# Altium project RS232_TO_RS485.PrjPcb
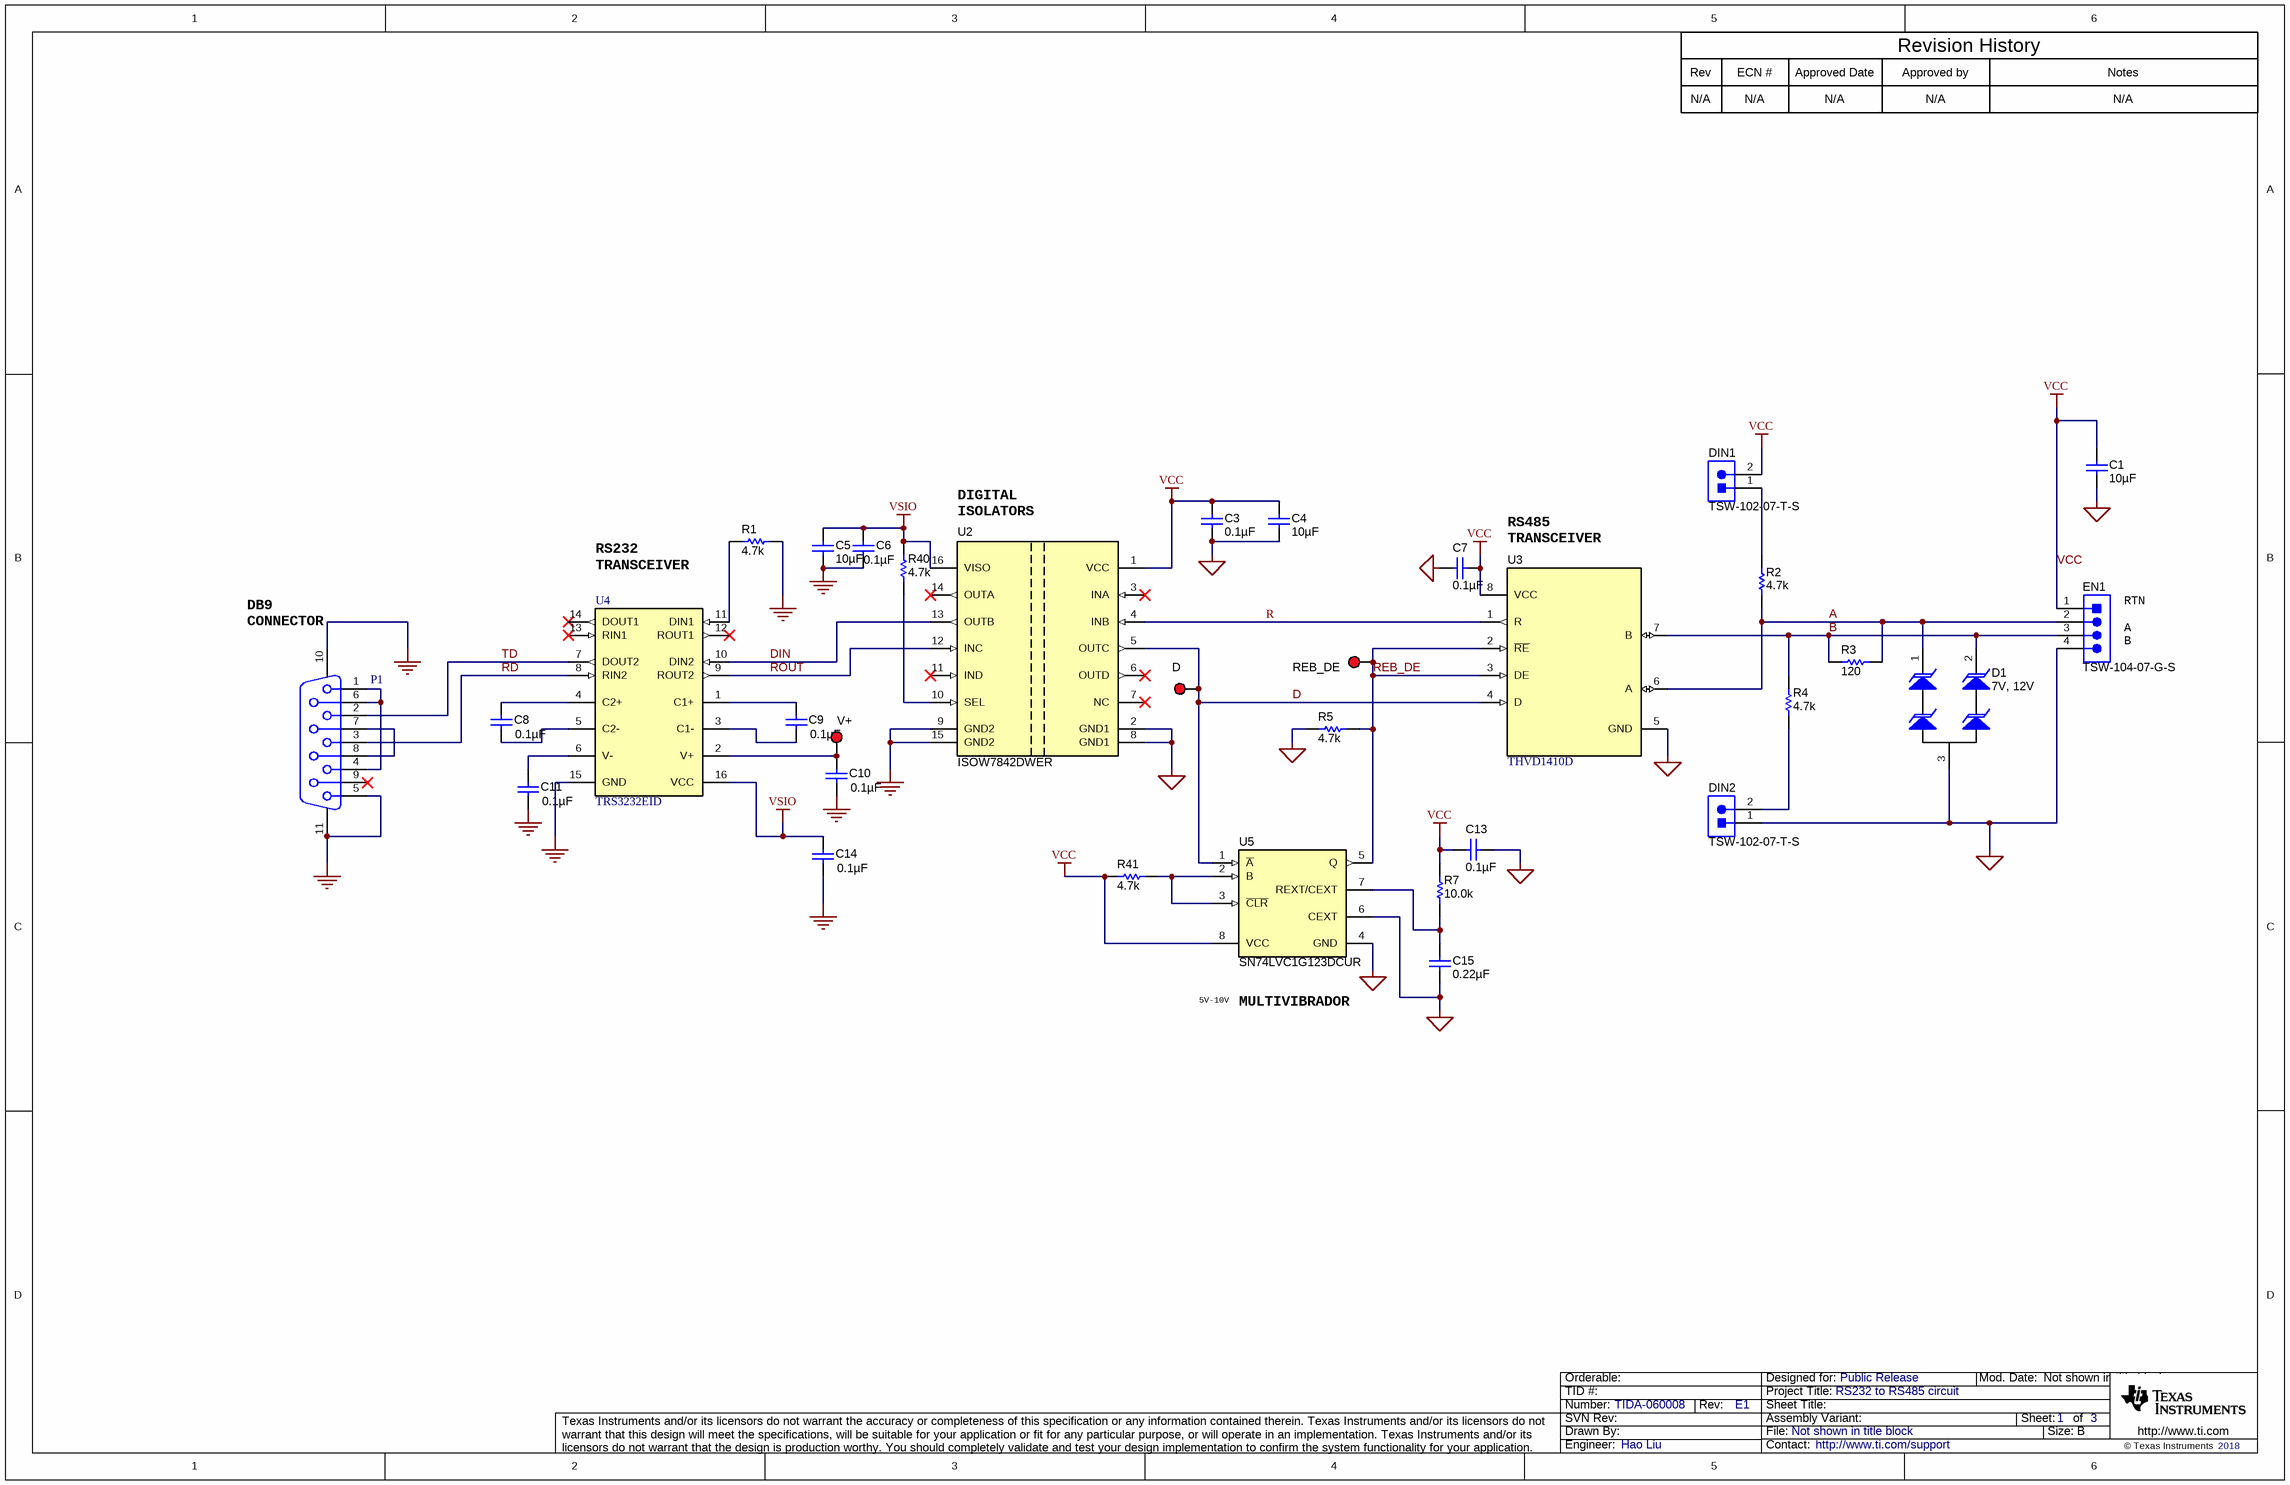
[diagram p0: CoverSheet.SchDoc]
TIDA: 060008; TechSupport: http://www.ti.com/support; SCH_Rev: E1; PRJ_Title: RS232 to RS485 circuit; PRJ_Number: TIDA-060008; PRJ_Engineer: Hao Liu; PRJ_Customer: Public Release; PCB_Rev: E1; PCB_Layout: Hao Liu; CopyrightYear: 2018
3 sheets, 49 parts. Net scope: global (net labels, ports and power ports of the same name join across sheets).
Board file: PCB.PcbDoc
Sheets:
  CoverSheet.SchDoc
  BlankSheet.SchDoc
  EVM_Hardware.SchDoc

## Sheet CoverSheet.SchDoc
size 431 x 279 mm; Date: Not shown in title block; ApprovedBy: Not shown in title block; CheckedBy: Not shown in title block; Author: Not shown in title block; CompanyName: Not shown in title block; Engineer: Not shown in title block; Organization: Not shown in title block; Address1: Not shown in title block; Address2: Not shown in title block; Address3: Not shown in title block; Address4: Not shown in title block; DocumentNumber: 1; Revision: Use project parameter SCH_Rev; SheetNumber: 1; SheetTotal: 3; PageSetup: Record=PageOptions¦CenterHorizontal=True¦CenterVertical=True¦PrintScale=1.00¦XCorrection=1.00¦YCorrection=1.00¦PrintKind=0¦BorderSize=5000000¦LeftOffset=0¦BottomOffset=0¦Orientation=2¦PaperLength=1000¦PaperWidth=1000¦Scale=100¦PaperSource=15¦PrintQuality=600¦MediaType=1¦DitherType=10¦PaperKind=Letter¦PrintScaleMode=1

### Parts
C1  ValueDisplayed: 10µF  [0805_HV]  (hidden comment: EMK212BJ106KG-T)
C3  ValueDisplayed: 0.1µF  [0603]  (hidden comment: GCM188R71C104KA37J)
C4  ValueDisplayed: 10µF  [0805_HV]  (hidden comment: GRM21BC80J106KE19L)
C5  ValueDisplayed: 10µF  [0805_HV]  (hidden comment: GRM21BC80J106KE19L)
C6  ValueDisplayed: 0.1µF  [0603]  (hidden comment: GCM188R71C104KA37J)
C7  ValueDisplayed: 0.1µF  [0603]  (hidden comment: GCM188R71C104KA37J)
C8  ValueDisplayed: 0.1µF  [0603]  (hidden comment: GCM188R71C104KA37J)
C9  ValueDisplayed: 0.1µF  [0603]  (hidden comment: GCM188R71C104KA37J)
C10  ValueDisplayed: 0.1µF  [0603]  (hidden comment: GCM188R71C104KA37J)
C11  ValueDisplayed: 0.1µF  [0603]  (hidden comment: GCM188R71C104KA37J)
C13  ValueDisplayed: 0.1µF  [0603]  (hidden comment: GCM188R71C104KA37J)
C14  ValueDisplayed: 0.1µF  [0603]  (hidden comment: GCM188R71C104KA37J)
C15  ValueDisplayed: 0.22µF  [0603]  (hidden comment: GRM188R70J224KA88D)
D  5000  [Keystone5000]  (value not drawn)
D1  value 7V, 12V  [SOT-23]  (hidden comment: SM712.TCT)
DIN1  TSW-102-07-T-S  [Samtec_TSW-102-07-T-S]
DIN2  TSW-102-07-T-S  [Samtec_TSW-102-07-T-S]
EN1  TSW-104-07-G-S  [TSW-104-07-G-S]
P1  1734354-1  [TE_1734354-1]  (value not drawn)
R1  ValueDisplayed: 4.7k  [0603]  (hidden comment: ERJ-3GEYJ472V)
R2  ValueDisplayed: 4.7k  [0603]  (hidden comment: ERJ-3GEYJ472V)
R3  ValueDisplayed: 120  [0603]  (hidden comment: CRCW0603120RJNEA)
R4  ValueDisplayed: 4.7k  [0603]  (hidden comment: ERJ-3GEYJ472V)
R5  ValueDisplayed: 4.7k  [0603]  (hidden comment: ERJ-3GEYJ472V)
R7  ValueDisplayed: 10.0k  [0603]  (hidden comment: RMCF0603FT10K0)
R40  ValueDisplayed: 4.7k  [0603]  (hidden comment: ERJ-3GEYJ472V)
R41  ValueDisplayed: 4.7k  [0603]  (hidden comment: ERJ-3GEYJ472V)
REB_DE  5000  [Keystone5000]  (value not drawn)
U2  ISOW7842DWER  [DWE0016A]
U3  THVD1410D  [D0008A_N]
U4  TRS3232EID  [D0016A_N]
U5  SN74LVC1G123DCUR  [DCU0008A_N]
V+  5000  [Keystone5000]  (value not drawn)

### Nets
GND: C5.2 C6.2 C10.2 C11.2 C14.2 P1.5 P1.10 P1.11 R1.2 U2.9(GND2) U2.15(GND2) U4.15(GND)
GND_SIGNAL: C1.2 C3.2 C4.2 C7.2 C13.1 C15.2 D1.3 DIN2.1 EN1.4 R5.1 U2.2(GND1) U2.8(GND1) U3.5(GND) U5.4(GND) U5.6(CEXT)
VCC: C1.1 C3.1 C4.1 C7.1 C13.2 DIN1.2 EN1.1 R7.2 R41.2 U2.1(VCC) U3.8(VCC) U5.8(VCC)
VSIO: C5.1 C6.1 C14.1 R40.2 U2.16(VISO) U4.16(VCC)
A: D1.1 EN1.2 R2.1 R3.2 U3.6(A)
B: D1.2 EN1.3 R3.1 R4.2 U3.7(B)
D: D.1 U2.5(OUTC) U3.4(D) U5.1(~{A})
DIN: U2.13(OUTB) U4.10(DIN2)
R: U2.4(INB) U3.1(R)
RD: P1.3 U4.8(RIN2)
REB_DE: R5.2 REB_DE.1 U3.2(~{RE}) U3.3(DE) U5.5(Q)
ROUT: U2.12(INC) U4.9(ROUT2)
TD: P1.2 U4.7(DOUT2)
NetC8_1: C8.1 U4.4(C2+)
NetC8_2: C8.2 U4.5(C2-)
NetC9_1: C9.1 U4.1(C1+)
NetC9_2: C9.2 U4.3(C1-)
NetC10_1: C10.1 U4.2(V+) V+.1
NetC11_1: C11.1 U4.6(V-)
NetC15_1: C15.1 R7.1 U5.7(REXT/CEXT)
NetDIN1_1: DIN1.1 R2.2
NetDIN2_2: DIN2.2 R4.1
NetP1_1: P1.1 P1.4 P1.6
NetP1_7: P1.7 P1.8
NetR1_1: R1.1 U4.11(DIN1)
NetR40_1: R40.1 U2.10(SEL)
NetR41_1: R41.1 U5.2(B) U5.3(~{CLR})

Not connected (* = marked no-connect by the designer): P1 9*; U2 3(INA)* 6(OUTD)* 7(NC)* 11(IND)* 14(OUTA)*; U4 12(ROUT1)* 13(RIN1)* 14(DOUT1)*

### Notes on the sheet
- Rev
- N/A
- ECN #
- Approved Date
- Approved by
- Revision History
- Notes
- DIGITAL
  ISOLATORS
- RS485
  TRANSCEIVER
- (near P1) DB9
  CONNECTOR
- (near R1) RS232
  TRANSCEIVER
- (near EN1) A
- (near EN1) RTN
- (near EN1) B
- 5V-10V
- (near U5) MULTIVIBRADOR

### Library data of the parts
C1 = EMK212BJ106KG-T: CAP, CERM, 10 µF, 16 V,+/- 10%, X5R, 0805; Manufacturer: Taiyo Yuden; Polarized: N; CompType: Capacitor; Value: 10uF; U/M: EA; Cap_F: 0.00001; Tolerance_%: 10; VDC_V: 16; Value2: 16V; TaMin_C: -55; TaMax_C: 85; Cap_Case: 0805; SizeArea_mm2: 2.5; SizeAreaWB_mm2: 6.75; SizeX_mm: 2; SizeY_mm: 1.25; SizeZ_mm: 1.45; AEC Category: Q200; Green_Lifecycle: Not Set; Green_REACh: Incomplete
C3 C6 C7 C13 = GCM188R71C104KA37J: CAP, CERM, 0.1 µF, 16 V,+/- 10%, X7R, AEC-Q200 Grade 1, 0603; Manufacturer: MuRata; Polarized: N; CompType: Capacitor; Value: 0.1uF; U/M: EA; Cap_F: 0.0000001; Tolerance_%: 10; VDC_V: 16; Value2: 16V; TaMin_C: -55; TaMax_C: 125; SizeArea_mm2: 1.28; SizeAreaWB_mm2: 4.68; SizeX_mm: 1.6; SizeY_mm: 0.8; SizeZ_mm: 1; AEC Category: Q200; AEC Qualified: Y; Green_Lifecycle: Active; Green_REACh: Passed
C4 C5 = GRM21BC80J106KE19L: CAP, CERM, 10 µF, 6.3 V,+/- 10%, X6S, 0805; Manufacturer: MuRata; Polarized: N; CompType: Capacitor; Value: 10uF; U/M: EA; Cap_F: 0.00001; Tolerance_%: 10; VDC_V: 6.3; Value2: 6.3V; TaMin_C: -55; TaMax_C: 105; Cap_Case: 0805; SizeArea_mm2: 2.5; SizeAreaWB_mm2: 6.75; SizeX_mm: 2; SizeY_mm: 1.25; SizeZ_mm: 1.45; AEC Category: Q200
C8-C11 C14 = GCM188R71C104KA37J: CAP, CERM, 0.1 µF, 16 V, +/- 10%, X7R, AEC-Q200 Grade 1, 0603; Manufacturer: MuRata; Polarized: N; CompType: Capacitor; Value: 0.1uF; U/M: EA; Cap_F: 0.0000001; Tolerance_%: 10; Value1: Unknown; VDC_V: 16; Value2: 16V; TaMin_C: -55; TaMax_C: 125; SizeArea_mm2: 1.28; SizeAreaWB_mm2: 4.68; SizeX_mm: 1.6; SizeY_mm: 0.8; SizeZ_mm: 1; AEC Category: Q200; AEC Qualified: Y
C15 = GRM188R70J224KA88D: CAP, CERM, 0.22 µF, 6.3 V,+/- 10%, X7R, 0603; Manufacturer: MuRata; Polarized: N; CompType: Capacitor; Value: 0.22uF; U/M: EA; Cap_F: 0.00000022; Tolerance_%: 10; VDC_V: 6.3; Value2: 6.3V; TaMin_C: -55; TaMax_C: 125; SizeArea_mm2: 1.28; SizeAreaWB_mm2: 4.68; SizeX_mm: 1.6; SizeY_mm: 0.8; SizeZ_mm: 1; AEC Category: Q200
D REB_DE V+ = 5000: Test Point, Miniature, Red, TH; Manufacturer: Keystone; CompType: Test Point Loop; ContactFinish: Silver
D1 = SM712.TCT: Asymmetrical TVS Diode for Extended Common-Mode RS-485, SOT-23; Manufacturer: Semtech; Symbol Creator: a0411947; SizeAreaWB_mm2: 14; SizeArea_mm2: 7.5; SizeX_mm: 2.5; SizeY_mm: 3; SizeZ_mm: 1.1
DIN1 DIN2 = TSW-102-07-T-S: Header, 2.54 mm, 2x1, Tin, TH; Manufacturer: Samtec; SymbolCreator: a0412235; Pitch_mm: 2.54; Gender: Male; Shrouded: N; Row_Count: 1; Current_A: 6.3; Voltage_V: 550; Cert_CSA: Y; Green_Lifecycle: Active; Green_REACh: Passed
EN1 = TSW-104-07-G-S: Header, 100mil, 4x1, Gold, TH; Manufacturer: Samtec; SymbolCreator: a0412235; Pitch_mm: 2.54; Gender: Male; Shrouded: N; Row_Count: 1; Current_A: 6.3; Voltage_V: 550; Cert_CSA: Y; Green_Lifecycle: Active; Green_REACh: Passed
P1 = 1734354-1: Receptacle, D-Sub, 9 Position, R/A, TH; Manufacturer: TE Connectivity; SymbolCreator: Altium; Gender: Female; ContactFinish: Gold; Green_Lifecycle: Active; Green_REACh: Passed
R1 = ERJ-3GEYJ472V: RES, 4.7 k, 5%, 0.1 W, AEC-Q200 Grade 0, 0603; Manufacturer: Panasonic; CompType: Resistor; Value: 4.7k; Res_ohm: 4700; Value_Code: 4k70; Tolerance_%: 5; Power_W: 0.1; Value2: 0.1W; VDC_V: 75; TempCo: 200 ppm/C; SizeArea_mm2: 1.28; SizeX_mm: 1.6; SizeY_mm: 0.8; SizeZ_mm: 1; EIA_Code: E24; U/M: EA; AEC Category: Q200; AEC Qualified: Y; AEC Grade: 0; Green_Lifecycle: Active; Green_REACh: Passed
R2 R4 R5 R40 R41 = ERJ-3GEYJ472V: RES, 4.7 k, 5%, 0.1 W, AEC-Q200 Grade 0, 0603; Manufacturer: Panasonic; CompType: Resistor; Value: 4.7k; U/M: EA; Power_W: 0.1; TempCo: 200 ppm/C; Tolerance_%: 5; Res_ohm: 4700; Value_Code: 4k70; Value2: 0.1W; VDC_V: 75; SizeArea_mm2: 1.28; SizeX_mm: 1.6; SizeY_mm: 0.8; SizeZ_mm: 1; EIA_Code: E24; AEC Category: Q200; AEC Qualified: Y; AEC Grade: 0; Green_Lifecycle: Active; Green_REACh: Passed
R3 = CRCW0603120RJNEA: RES, 120, 5%, 0.1 W, 0603; Manufacturer: Vishay-Dale; CompType: Resistor; Value: 120; Value_Code: 120R; Tolerance_%: 5; Power_W: 0.1; Value2: 0.1W; VDC_V: 75; TempCo: 200 ppm/C; SizeArea_mm2: 1.28; SizeX_mm: 1.6; SizeY_mm: 0.8; SizeZ_mm: 1; EIA_Code: E24; U/M: EA; AEC Category: Q200; Green_Lifecycle: Active; Green_REACh: Passed
R7 = RMCF0603FT10K0: RES, 10.0 k, 1%, 0.1 W, AEC-Q200 Grade 0, 0603; Manufacturer: Stackpole Electronics Inc; CompType: Resistor; Value: 10.0k; Res_ohm: 10000; Value_Code: 10k0; Tolerance_%: 1; Power_W: 0.1; Value2: 0.1W; VDC_V: 75; TempCo: 100 ppm/C; SizeArea_mm2: 1.28; SizeX_mm: 1.6; SizeY_mm: 0.8; EIA_Code: E96; U/M: EA; AEC Category: Q200; AEC Qualified: Y; AEC Grade: 0
U2 = ISOW7842DWER: High-Performance, 5000-VRMS Reinforced Quad-Channel Digital Isolators With Integrated High-Efficiency, Low-Emissions DC-DC Converter, DWE0016A (SOIC-16); Manufacturer: Texas Instruments; SymbolCreator: Altium; SizeArea_mm2: 106.09; SizeAreaWB_mm2: 151.29; SizeX_mm: 10.3; SizeZ_mm: 2.65; CompType: IC; U/M: EA
U3 = CMP-0065060-3: 3.3-V to 5-V RS-485 Transceivers With +/-18-kV IEC ESD Protection, D0008A (SOIC-8); Manufacturer: Texas Instruments; Alternate PartNumber: THVD1410DR; SizeX_mm: 4.9; SizeY_mm: 6.2; CompType: IC; SizeZ_mm: 1.75; SizeArea_mm2: 30.38; SizeAreaWB_mm2: 56.58; AEC Category: Q200; AEC Qualified: N
U4 = TRS3232EID: 3-V to 5.5-V Multichannel RS-232 Line Driver / Receiver with ±15-kV IEC ESD Protection, -40 to 85 degC, 16-Pin SOIC (D), Green (RoHS & no Sb/Br); Manufacturer: Texas Instruments; Alternate PartNumber: Equivalent; Drivers Per Package: 2; Supply Voltage(s)(V): 3.3 or 5.0; ESD HBM(kV): +/-15; ICC(Max)(mA): 1; Single Supply: TRUE
U5 = SN74LVC1G123DCUR: Single Retriggerable Monostable Multivibrator with Schmitt-Trigger Inputs, DCU0008A, LARGE T&R; Manufacturer: Texas Instruments; Alternate PartNumber: Equivalent; VCC(Min)(V): 1.65; VCC(Max)(V): 5.5; Output Type: CMOS; ICC @ Nom Voltage(Max)(mA): 0.02; Input Type: CMOS/TTL; Bits(#): 1; F @ Nom Voltage(Max)(Mhz): 150; Rating: Catalog; Technology Family: LVC; Voltage(Nom)(V): 1.8,2.5,3.3,5; Schmitt Trigger: Yes; Output Drive (IOL/IOH)(Max)(mA): 32/-32; tpd @ Nom Voltage(Max)(ns): 34,11,8,5.5; Logic: True; 3-State Output: No

## Sheet BlankSheet.SchDoc
size 431 x 279 mm; Date: Not shown in title block; ApprovedBy: Not shown in title block; CheckedBy: Not shown in title block; Author: Not shown in title block; CompanyName: Not shown in title block; Engineer: Not shown in title block; Organization: Not shown in title block; Address1: Not shown in title block; Address2: Not shown in title block; Address3: Not shown in title block; Address4: Not shown in title block; DocumentNumber: 1; Revision: Use project parameter SCH_Rev; SheetNumber: 2; SheetTotal: 3; PageSetup: Record=PageOptions¦CenterHorizontal=True¦CenterVertical=True¦PrintScale=1.00¦XCorrection=1.00¦YCorrection=1.00¦PrintKind=0¦BorderSize=5000000¦LeftOffset=0¦BottomOffset=0¦Orientation=2¦PaperLength=1000¦PaperWidth=1000¦Scale=100¦PaperSource=15¦PrintQuality=600¦MediaType=1¦DitherType=10¦PaperKind=Letter¦PrintScaleMode=1

## Sheet EVM_Hardware.SchDoc
size 431 x 279 mm; Date: Not shown in title block; ApprovedBy: Not shown in title block; CheckedBy: Not shown in title block; Author: Not shown in title block; CompanyName: Not shown in title block; Engineer: Not shown in title block; Organization: Not shown in title block; Address1: Not shown in title block; Address2: Not shown in title block; Address3: Not shown in title block; Address4: Not shown in title block; DocumentNumber: 1; Revision: Use project parameter SCH_Rev; SheetNumber: 3; SheetTotal: 3; PageSetup: Record=PageOptions¦CenterHorizontal=True¦CenterVertical=True¦PrintScale=1.00¦XCorrection=1.00¦YCorrection=1.00¦PrintKind=0¦BorderSize=5000000¦LeftOffset=0¦BottomOffset=0¦Orientation=2¦PaperLength=1000¦PaperWidth=1000¦Scale=100¦PaperSource=15¦PrintQuality=600¦MediaType=1¦DitherType=10¦PaperKind=Letter¦PrintScaleMode=1
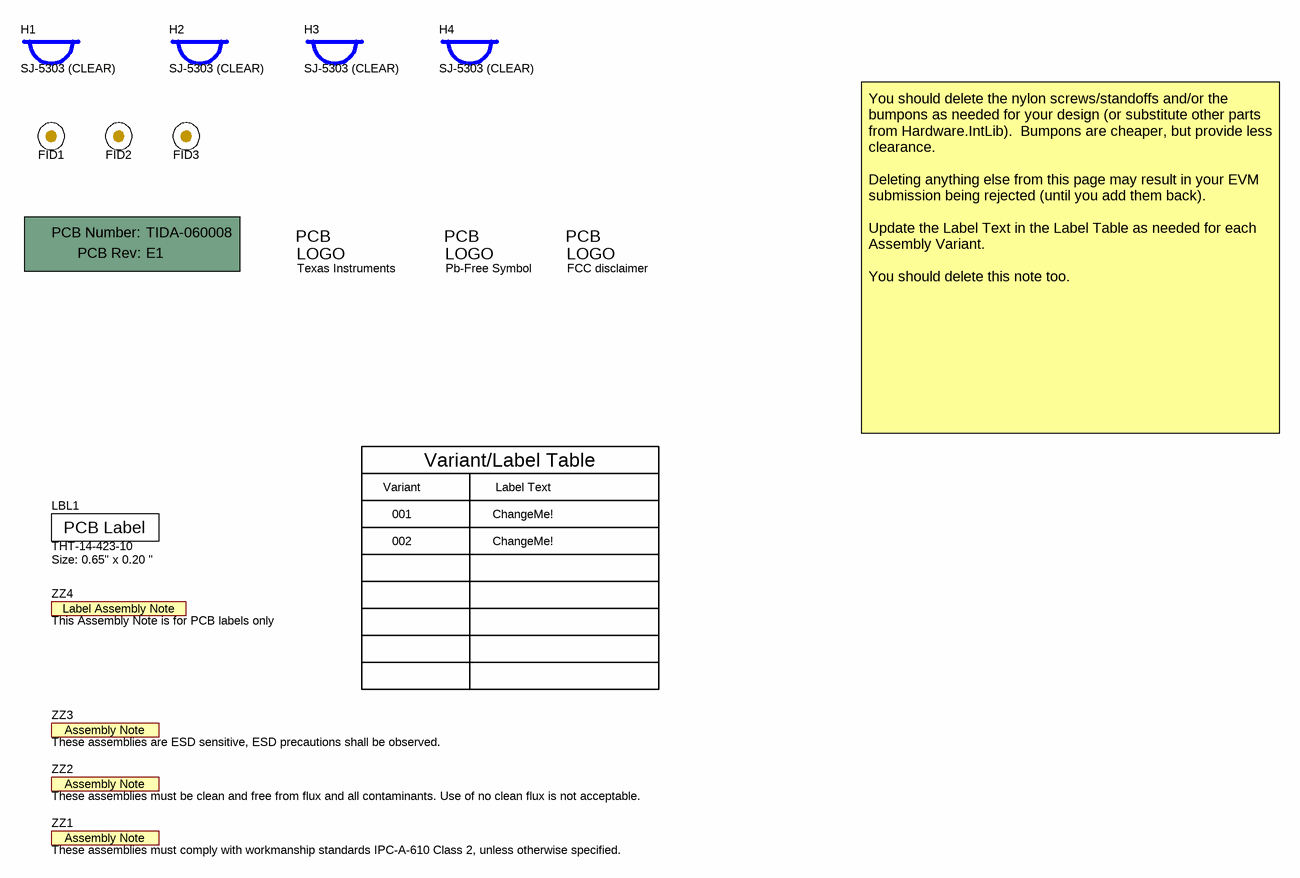
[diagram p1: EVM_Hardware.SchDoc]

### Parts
!PCB1  Printed Circuit Board  (value not drawn)  (mechanical)
FID1  Fiducial  [Fiducial10-20]  (value not drawn)
FID2  Fiducial  [Fiducial10-20]  (value not drawn)
FID3  Fiducial  [Fiducial10-20]  (value not drawn)
H1  SJ-5303 (CLEAR)  [Bumpon_SJ5003Transparent]
H2  SJ-5303 (CLEAR)  [Bumpon_SJ5003Transparent]
H3  SJ-5303 (CLEAR)  [Bumpon_SJ5003Transparent]
H4  SJ-5303 (CLEAR)  [Bumpon_SJ5003Transparent]
LBL1  THT-14-423-10  Note: Size: 0.65" x 0.20 "  [Label_650x200]
Logo1  Texas Instruments  [TI_Stacked_Overlay_Small]  (no BOM)
Logo2  Pb-Free Symbol  [Pb-Free_Overlay_Small]  (no BOM)
Logo3  FCC disclaimer  [FCC_disclaimer]  (no BOM)
ZZ1  These assemblies must comply with workmanship standards IPC-A-610 Class 2, unless otherwise specified.  [AssemblyNote]  (no BOM)
ZZ2  These assemblies must be clean and free from flux and all contaminants. Use of no clean flux is not acceptable.  [AssemblyNote]  (no BOM)
ZZ3  These assemblies are ESD sensitive, ESD precautions shall be observed.  [AssemblyNote]  (no BOM)
ZZ4  This Assembly Note is for PCB labels only  [AssemblyNoteLabel]  (no BOM)

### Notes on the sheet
- Variant
- Variant/Label Table
- Label Text
- You should delete the nylon screws/standoffs and/or the bumpons as needed for your design (or substitute other parts from Hardware.IntLib).  Bumpons are cheaper, but provide less clearance.
  Deleting anything else from this page may result in your EVM submission being rejected (until you add them back).
  Update the Label Text in the Label Table as needed for each Assembly Variant.
  You should delete this note too.
- 001
- 002
- ChangeMe!

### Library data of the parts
!PCB1 = CMP-0003618-2: Manufacturer: Any; PartNumber: TIDA-060008
FID1-FID3 = CMP-0077181-1: Fiducial mark.  There is nothing to buy or mount.
H1-H4 = CMP-0003620-1: Bumpon, Hemisphere, 0.44 X 0.20, Clear; Manufacturer: 3M
LBL1 = CMP-0003625-1: Thermal Transfer Printable Labels, 0.650" W x 0.200" H - 10,000 per roll; Manufacturer: Brady; CompType: Label
Logo1 = CMP-0074838-1: Texas Instrument Corporate Signature; SymbolCreator: a0412235; Lib Reference: TI_Logo; Library Reference: Logo
Logo2 = CMP-0074839-1: SymbolCreator: a0412235; Library Reference: Logo
Logo3 = CMP-0074847-1: FCC_disclaimer; Library Reference: Logo
ZZ1 = CMP-0077238-1
ZZ2 = CMP-0077237-1
ZZ3 = CMP-0077236-1
ZZ4 = CMP-0003616-3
